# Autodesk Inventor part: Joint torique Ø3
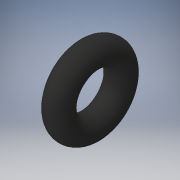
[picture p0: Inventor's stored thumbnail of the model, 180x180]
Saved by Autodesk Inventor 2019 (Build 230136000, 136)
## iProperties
Created: 2018-06
Part Number: Joint torique Ø3
Material: Caoutchouc
Document SubType Name: Modeling
Designer: Fabian Perrée
Density: 0.93 g/cm^3
Appearance: Caoutchouc - Noir
Author: Fabian Perrée
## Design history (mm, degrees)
sketch "Esquisse1"
  geometry: L1 (-2.1, 0)-(2.1, 0) reference; C1 r 1.5 at (0, 3.75); 1 further point
  constraints: 1 centre point, 1 vertical alignment
  dimensions: "d0" = 3 diameter of C1; "d1" = 3.75 distance of point (0, 0) C1.centre
revolve "Révolution1" sketch "Esquisse1" stored, may be unused: angle "d2" = 90 deg
node "Solide1"
